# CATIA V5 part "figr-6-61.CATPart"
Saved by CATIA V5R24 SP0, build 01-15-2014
Part number: Part1
Bounding box of the stored display mesh (mm): x -50.648 to 50.648, y -72.183 to 72.183, z -40 to 40
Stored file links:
  D:\KAVITA\CATIA V5-6R2014 Project_ Kavita\CATIA V5-6R2014_partfiles\Partfiles\c06_catia_v5-6r2014_prt\figr-6-61.CATPart
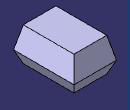
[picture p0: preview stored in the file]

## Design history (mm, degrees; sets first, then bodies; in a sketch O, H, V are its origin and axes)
Body1 (main body)
  Sketch1 on xy-plane, origin (0, 0, 0), H (1, 0, 0), V (0, 1, 0)
    line L1 (-50.6478, 72.1832) -> (50.6478, 72.1832)
    line L2 (50.6478, 72.1832) -> (50.6478, -72.1832)
    line L3 (50.6478, -72.1832) -> (-50.6478, -72.1832)
    line L4 (-50.6478, -72.1832) -> (-50.6478, 72.1832)
    axis line L5 (50.6478, -72.1832) -> (-50.6478, 72.1832)
    horizontal: L1 H, L3 H
    vertical: L2 V, L4 V
    midpoint: O L5
  Pad1: profile Sketch1, direction (0, 0, 1), length 40, mirrored extent
  Draft1: Angle 30, Neutral xy-plane, PullDir (0, 0, 1), SupportToDraft (face of Pad1; face of Pad1)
